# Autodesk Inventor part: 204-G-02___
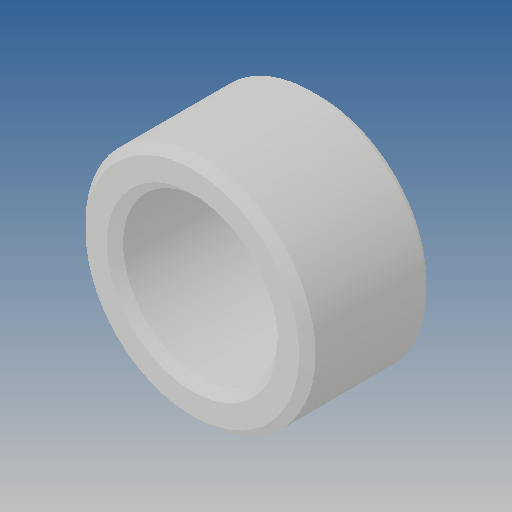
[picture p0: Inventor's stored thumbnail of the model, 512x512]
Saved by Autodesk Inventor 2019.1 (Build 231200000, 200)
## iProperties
Created: 2010-06
Part Number: 204-G-02___
Material: Ogólny
Document SubType Name: Modeling
Designer: CADENGINEERING4
Density: 1 g/cm^3
Appearance: Domyślna
Author: CADENGINEERING4
Revision Number: ANY
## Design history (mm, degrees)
feature "NONE"
node "Bryła1"
